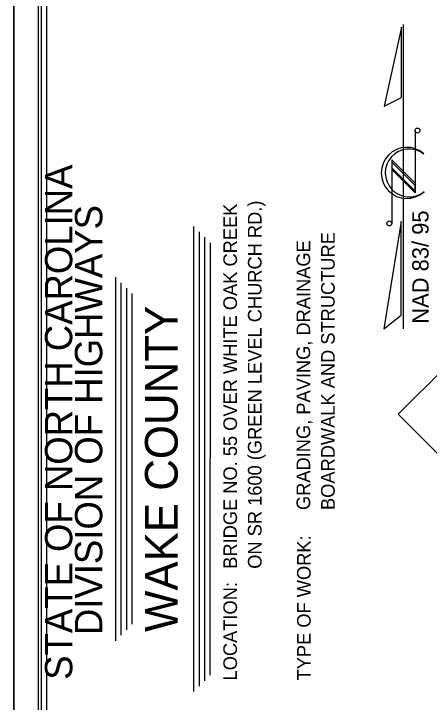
# Model space of a CAD drawing. Extents: x 2026893 to 2039781, y 729195 to 739590.
# Drawn here: x 2026893 to 2028226, y 736122 to 738328 of the extents above; entities that cross this region are included whole.
import ezdxf

# ---------------------------------------------------------------- set-up
doc = ezdxf.new("R2010")
doc.units = 0
for name, color, linetype in [('Old_Level_20', 7, 'Continuous'), ('Old_Level_22', 7, 'Continuous'), ('Sheet Cutting Line CELL', 7, 'Continuous'), ('Sheet Data Field CELL', 7, 'Continuous'), ('Sheet Plot Border Inside CELL', 7, 'Continuous'), ('Sheet Plot Border Outside CELL', 7, 'Continuous'), ('Sheet Title CELL', 7, 'Continuous'), ('Sheet Title Data Points CELL', 7, 'Continuous')]:
    doc.layers.add(name, color=color, linetype=linetype)

msp = doc.modelspace()

# ---------------------------------------------------------------- linework, layer by layer
at = {"layer": 'Old_Level_20'}
for p, q in [((2028143.1, 737318.3), (2028143.1, 738293.3)), ((2028179.9, 737954), (2028179.9, 737753.9)), ((2028207.5, 737879.4), (2028208.5, 737878.7)), ((2028179.9, 737785.1), (2028105.3, 737859.6)), ((2028105.3, 737859.6), (2028105.3, 737656.2)), ((2028179.9, 737777.7), (2028105.3, 737852.3)), ((2028105.3, 737852.3), (2028105.3, 737834)), ((2028179.9, 737759.4), (2028105.3, 737834)), ((2028105.3, 737834), (2028179.9, 737759.4)), ((2028179.9, 737753.9), (2028105.3, 737828.4)), ((2028179.9, 737759.4), (2028179.9, 737777.7))]:
    msp.add_line(p, q, dxfattribs=at)
for points in [[(2028136.4, 738284.7), (2028080.7, 738031.5), (2028136.4, 738059.7)], [(2028135.2, 737661.8), (2028080, 737318.3), (2028135.2, 737361.8)]]:
    msp.add_lwpolyline(points, close=True, dxfattribs=at)
for centre in [(2028187.8, 737953.8), (2028097.4, 737655.9)]:
    msp.add_circle(centre, 7.95, dxfattribs=at)
for centre, radius, start, end in [((2028153.5, 737818), 81.9, 47.84, 312.3941), ((2028161.4, 737818), 76.8, 53.095, 308.6287)]:
    msp.add_arc(centre, radius, start, end, dxfattribs=at)
at = {"layer": 'Old_Level_22'}
for p, q in [((2028294.4, 737212.4), (2028126.3, 737044.3)), ((2028126.3, 737044.3), (2029187.1, 735983.6))]:
    msp.add_line(p, q, dxfattribs=at)
at = {"layer": 'Sheet Cutting Line CELL'}
msp.add_line((2026892.9, 733695.9), (2026892.9, 739589.9), dxfattribs=at)
at = {"layer": 'Sheet Plot Border Inside CELL'}
msp.add_lwpolyline([(2030664.3, 733741.4), (2030664.3, 739574.2), (2026971.4, 739574.2), (2026971.4, 733741.4)], close=True, dxfattribs=at)
at = {"layer": 'Sheet Plot Border Outside CELL'}
msp.add_lwpolyline([(2026892.9, 739589.9), (2026892.9, 733695.9), (2030742.8, 733695.9), (2030742.8, 739589.9)], close=True, dxfattribs=at)
at = {"layer": 'Sheet Title CELL'}
for p, q in [((2027470.8, 736155.6), (2027470.9, 737646.6)), ((2027488.3, 736173.1), (2027488.4, 737629.1)), ((2027505.9, 736190.6), (2027505.8, 737611.6)), ((2027523.3, 736208.1), (2027523.4, 737594.1)), ((2027220.3, 736318.8), (2027220.2, 737483.5)), ((2027237.7, 736336.3), (2027237.8, 737466)), ((2027255.3, 736353.8), (2027255.2, 737448.5)), ((2027272.8, 736371.3), (2027272.7, 737431))]:
    msp.add_line(p, q, dxfattribs=at)
for points in [[(2026980.4, 739495.5), (2026980.3, 734315.4)], [(2026997.9, 739477.9), (2026997.9, 734508)]]:
    msp.add_lwpolyline(points, dxfattribs=at)
at = {"layer": 'Sheet Title Data Points CELL'}
for p, q in [((2027609, 737326.7), (2027609, 737326.7)), ((2027418.7, 736906.5), (2027418.7, 736906.5))]:
    msp.add_line(p, q, dxfattribs=at)

# ---------------------------------------------------------------- texts
at = {"layer": 'Old_Level_20'}
msp.add_text('NAD 83/ 95', height=52.5, rotation=90, dxfattribs=at).set_placement((2028223.4, 737334.6))
at = {"layer": 'Sheet Data Field CELL'}
for s, height, p in [('BRIDGE NO. 55 OVER WHITE OAK CREEK', 43.75, (2027608.9, 736549.2)), ('ON SR 1600 (GREEN LEVEL CHURCH RD.)', 43.75, (2027687.7, 736549.2)), ('BOARDWALK AND STRUCTURE', 43.75, (2027922.3, 736737.5)), ('GRADING, PAVING, DRAINAGE', 43.75, (2027843.6, 736737.5)), ('WAKE COUNTY', 105, (2027418.7, 736346.7))]:
    msp.add_text(s, height=height, rotation=90, dxfattribs=at).set_placement(p)
at = {"layer": 'Sheet Title CELL'}
for s, height, p in [('STATE OF NORTH CAROLINA', 87.5, (2027080.5, 736193.5)), ('DIVISION OF HIGHWAYS', 87.5, (2027176.7, 736336.7)), ('TYPE OF WORK:', 43.75, (2027845.2, 736191.3)), ('LOCATION: ', 43.75, (2027608.9, 736191.3))]:
    msp.add_text(s, height=height, rotation=90, dxfattribs=at).set_placement(p)

doc.saveas('drawing.dxf')
